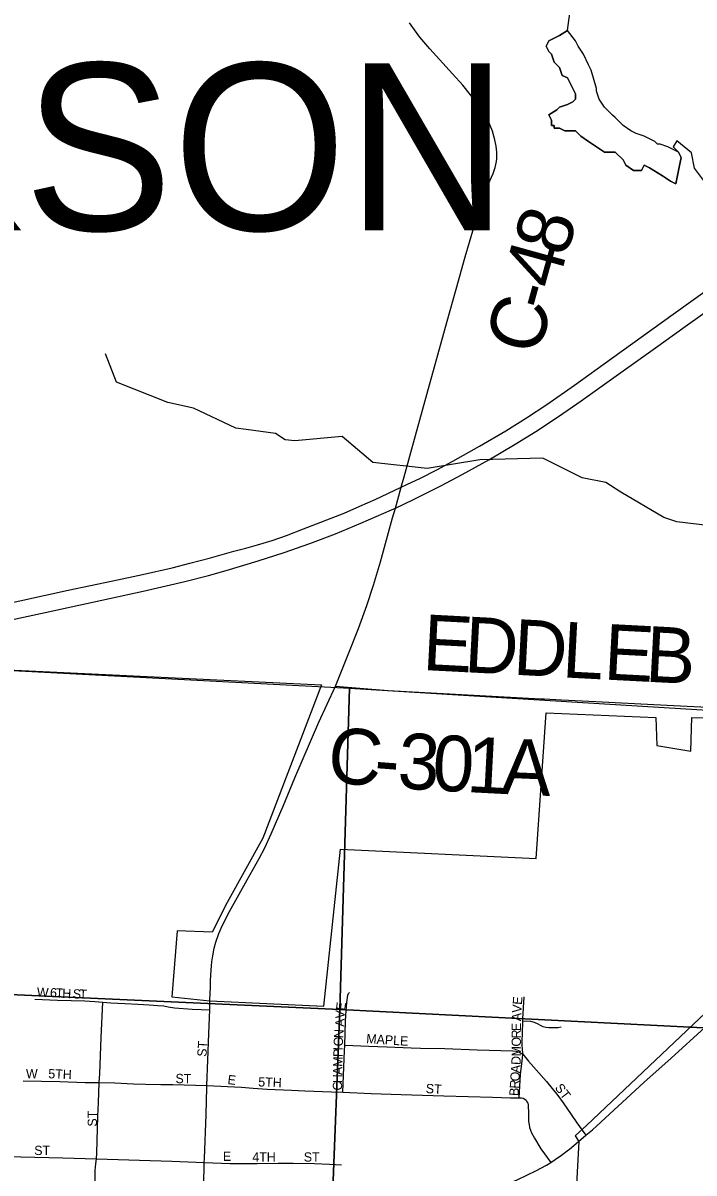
# Model space of a CAD drawing. Extents: x 0 to 34, y 0 to 22.
# Drawn here: x 4.796 to 5.481, y 18.295 to 19.468 of the extents above; entities that cross this region are included whole.
import ezdxf

# ---------------------------------------------------------------- set-up
doc = ezdxf.new("R2010")
doc.units = 0
for name, color, linetype in [('GM_X_City_Street', 7, 'Continuous'), ('GM_X_City_Street_Text', 7, 'Continuous'), ('GM_X_Corporation', 7, 'Continuous'), ('GM_X_County_Road', 7, 'Continuous'), ('GM_X_County_Road_Text', 7, 'Continuous'), ('GM_X_Minor_Lake', 7, 'Continuous'), ('GM_X_Minor_River', 7, 'Continuous'), ('GM_X_Section', 7, 'Continuous'), ('GM_X_State_Route', 7, 'Continuous'), ('GM_X_Township_Text', 7, 'Continuous')]:
    doc.layers.add(name, color=color, linetype=linetype)

msp = doc.modelspace()

# ---------------------------------------------------------------- linework, layer by layer
at = {"layer": 'GM_X_City_Street'}
for points in [[(4.8082, 18.4724), (4.8315, 18.4715), (4.8592, 18.4706), (4.8694, 18.4701), (4.8776, 18.4693)], [(4.9867, 18.4617), (4.987, 18.4717)], [(5.1257, 18.4562), (5.1265, 18.469), (5.1276, 18.4767), (5.1283, 18.4783), (5.1292, 18.4794)], [(5.306, 18.4503), (5.3061, 18.4523), (5.3074, 18.4749)], [(4.8741, 18.3874), (4.8746, 18.3964), (4.8761, 18.4333), (4.8776, 18.4693)], [(4.8776, 18.4693), (4.8859, 18.4688), (4.9001, 18.4681), (4.9135, 18.4673), (4.925, 18.4668), (4.9339, 18.4661), (4.9398, 18.4655), (4.9445, 18.4646), (4.9508, 18.4636), (4.9688, 18.4624), (4.9781, 18.4619), (4.9867, 18.4617)], [(4.9839, 18.3844), (4.9847, 18.4104), (4.9857, 18.4376), (4.9867, 18.4617)], [(5.1245, 18.4256), (5.1252, 18.4498), (5.1257, 18.4562)], [(5.3061, 18.4164), (5.3057, 18.4224), (5.3055, 18.4245), (5.3054, 18.4306), (5.3057, 18.4368), (5.306, 18.4503)], [(5.306, 18.4503), (5.3139, 18.4501), (5.3177, 18.4491), (5.3213, 18.4474), (5.3239, 18.4458), (5.3267, 18.4446), (5.3297, 18.4439), (5.3328, 18.4436), (5.339, 18.4435), (5.3421, 18.4437), (5.3451, 18.4442)], [(5.1225, 18.3775), (5.1243, 18.4201), (5.1245, 18.4256)], [(5.1245, 18.4256), (5.149, 18.4246), (5.1675, 18.4239), (5.1922, 18.4229), (5.2016, 18.4226), (5.2265, 18.4221), (5.2596, 18.4208), (5.2961, 18.4197), (5.2992, 18.4193), (5.302, 18.4186), (5.3061, 18.4164)], [(5.3023, 18.372), (5.3039, 18.3958), (5.3057, 18.4122), (5.3061, 18.4164)], [(5.3061, 18.4164), (5.312, 18.4093), (5.3302, 18.3884), (5.3419, 18.3741), (5.3474, 18.3668), (5.3554, 18.3549)], [(4.7965, 18.3893), (4.8337, 18.3884), (4.8595, 18.3876), (4.8717, 18.3874), (4.8741, 18.3874)], [(4.8711, 18.3097), (4.8717, 18.3153), (4.8727, 18.3532), (4.8732, 18.3666), (4.8741, 18.3874)], [(4.8741, 18.3874), (4.89, 18.387), (4.9089, 18.3863), (4.9212, 18.3859), (4.9367, 18.3855), (4.9491, 18.3854), (4.9839, 18.3844)], [(4.9811, 18.3058), (4.9813, 18.3101), (4.983, 18.3548), (4.9838, 18.3825), (4.9839, 18.3844)], [(4.9839, 18.3844), (5.019, 18.3827), (5.0311, 18.3817), (5.0452, 18.3808), (5.07, 18.3796), (5.0836, 18.3789), (5.111, 18.3779), (5.1225, 18.3775)], [(5.1225, 18.3775), (5.1513, 18.3763), (5.1822, 18.3753), (5.2256, 18.3738), (5.2752, 18.3725), (5.2845, 18.3723), (5.2937, 18.372), (5.3023, 18.372)], [(5.3023, 18.372), (5.3031, 18.3719), (5.3049, 18.3717), (5.3064, 18.3714), (5.3082, 18.3705), (5.3094, 18.3694), (5.3104, 18.3679), (5.3111, 18.3664), (5.3115, 18.365), (5.3117, 18.3632), (5.3119, 18.3568), (5.3119, 18.3507), (5.3121, 18.3476), (5.3125, 18.3446), (5.3131, 18.3417), (5.314, 18.3388), (5.3151, 18.336), (5.3179, 18.3306), (5.3245, 18.32), (5.3347, 18.3059)], [(5.3554, 18.3549), (5.3612, 18.3464), (5.3667, 18.3389), (5.3706, 18.3337)], [(5.3347, 18.3059), (5.3392, 18.3089), (5.3455, 18.3134), (5.3528, 18.3188)], [(4.7094, 18.3139), (4.7939, 18.3118), (4.8368, 18.3107), (4.8711, 18.3097)], [(4.8682, 18.2305), (4.8687, 18.2363), (4.8694, 18.2629), (4.8698, 18.2978), (4.8705, 18.3045), (4.8711, 18.3097)], [(4.8711, 18.3097), (4.9481, 18.3074), (4.9728, 18.3064), (4.9811, 18.3058)], [(4.98, 18.2664), (4.981, 18.2999), (4.9811, 18.3058)], [(4.9811, 18.3058), (5.0075, 18.305), (5.0352, 18.305), (5.0567, 18.3052), (5.072, 18.3051), (5.0935, 18.3048), (5.1088, 18.3042), (5.1211, 18.3034)], [(5.1151, 18.2271), (5.1191, 18.2276), (5.1284, 18.2294), (5.1375, 18.2316), (5.1525, 18.2361), (5.2263, 18.2613), (5.2647, 18.2746), (5.2852, 18.2822), (5.2997, 18.288), (5.311, 18.2933), (5.3194, 18.2975), (5.3303, 18.3032), (5.3347, 18.3059)]]:
    msp.add_lwpolyline(points, dxfattribs=at)
at = {"layer": 'GM_X_Corporation'}
for points in [[(4.7237, 18.8109), (5.1009, 18.7931), (5.0408, 18.6366), (5.0045, 18.5712), (4.9891, 18.5408), (4.9534, 18.542), (4.948, 18.4748), (4.987, 18.4706), (5.1033, 18.4653), (5.12, 18.6253), (5.3198, 18.6158), (5.33, 18.7645), (5.4418, 18.7598), (5.443, 18.7312), (5.4775, 18.7253), (5.4787, 18.7598), (5.7821, 18.7586)], [(5.6005, 18.5608), (5.3716, 18.3439), (5.3597, 18.3332), (5.3632, 18.3273), (5.329, 17.6967)]]:
    msp.add_lwpolyline(points, dxfattribs=at)
at = {"layer": 'GM_X_County_Road'}
for points in [[(5.1151, 18.7918), (5.1294, 18.8274), (5.1385, 18.8505), (5.1469, 18.8739), (5.1537, 18.8946), (5.1608, 18.9184), (5.1733, 18.9633), (5.1761, 18.9733), (5.182, 18.9945), (5.1824, 18.996), (5.185, 19.0052), (5.1967, 19.0471), (5.2081, 19.089), (5.2291, 19.1637), (5.2382, 19.1966), (5.2474, 19.2295), (5.2561, 19.2593), (5.2612, 19.2772), (5.2649, 19.2889), (5.2672, 19.2946), (5.2708, 19.3031), (5.2758, 19.3145), (5.2778, 19.3205), (5.2786, 19.3236), (5.2792, 19.3267), (5.2795, 19.3298), (5.2796, 19.333), (5.2795, 19.3361), (5.2789, 19.3424), (5.2777, 19.3486), (5.2751, 19.3576), (5.273, 19.3635), (5.2704, 19.3692), (5.2673, 19.3746), (5.2639, 19.3798), (5.2585, 19.3874), (5.2529, 19.3948), (5.245, 19.4045), (5.2345, 19.4159), (5.2114, 19.4417), (5.2011, 19.4536), (5.1956, 19.4608), (5.1907, 19.4682)], [(4.987, 18.4717), (4.9875, 18.4846), (4.9875, 18.4908), (4.9879, 18.4974), (4.9884, 18.5065), (4.9889, 18.5106), (4.9898, 18.5167), (4.9913, 18.5244), (4.9929, 18.5305), (4.996, 18.5394), (4.9997, 18.548), (5.0069, 18.5618), (5.0251, 18.5943), (5.0373, 18.6158), (5.043, 18.6268), (5.0494, 18.6409), (5.0615, 18.6694), (5.0735, 18.698), (5.0982, 18.7549), (5.1151, 18.7918)], [(5.1151, 18.7918), (5.1689, 18.7871), (5.2188, 18.7844), (5.3246, 18.7788)], [(5.3246, 18.7788), (5.328, 18.7787), (5.3455, 18.7777), (5.3805, 18.776), (5.4397, 18.773), (5.4805, 18.771), (5.5819, 18.766), (5.5842, 18.7659), (5.6253, 18.7634), (5.637, 18.7629), (5.6439, 18.7625), (5.6526, 18.7624), (5.6595, 18.7622), (5.6719, 18.7626), (5.6733, 18.7627), (5.6792, 18.7633), (5.6872, 18.7642), (5.6892, 18.7644), (5.6965, 18.765), (5.7135, 18.766), (5.7139, 18.766)], [(5.3706, 18.3337), (5.3771, 18.3393), (5.4295, 18.3876), (5.4574, 18.4124), (5.4918, 18.4437), (5.5399, 18.4876), (5.6294, 18.5692), (5.6663, 18.6024), (5.7055, 18.6377), (5.7331, 18.6628)], [(5.3528, 18.3188), (5.3539, 18.3196), (5.3581, 18.3232), (5.3631, 18.3273), (5.3706, 18.3337)]]:
    msp.add_lwpolyline(points, dxfattribs=at)
at = {"layer": 'GM_X_Minor_Lake'}
for points in [[(5.3517, 19.4604), (5.3436, 19.455), (5.3382, 19.4523), (5.3328, 19.4496), (5.3301, 19.4442), (5.3328, 19.4388), (5.3355, 19.4361), (5.3382, 19.428), (5.3436, 19.4226), (5.3463, 19.4145), (5.3517, 19.4118), (5.3598, 19.3956), (5.3598, 19.3902), (5.3571, 19.3875), (5.3517, 19.3848), (5.3436, 19.3821), (5.3409, 19.3794), (5.3328, 19.3741), (5.3355, 19.3687), (5.3355, 19.3633), (5.3382, 19.3633), (5.3382, 19.3606), (5.3409, 19.3606), (5.3436, 19.3606), (5.349, 19.3579), (5.3571, 19.3579), (5.3598, 19.3579), (5.3652, 19.3525), (5.3733, 19.3471), (5.3814, 19.3417), (5.3895, 19.3363), (5.4003, 19.3363), (5.4084, 19.3282), (5.4111, 19.3228), (5.4192, 19.3174), (5.4273, 19.3174), (5.43, 19.3228), (5.4354, 19.3201), (5.4488, 19.312), (5.4569, 19.3066), (5.4623, 19.3039), (5.465, 19.3174), (5.4677, 19.3309), (5.465, 19.3363)], [(5.4596, 19.3417), (5.465, 19.3363), (5.4677, 19.3309), (5.465, 19.3174), (5.4623, 19.3039), (5.4569, 19.3066), (5.4488, 19.312), (5.4354, 19.3201), (5.43, 19.3228), (5.4273, 19.3174), (5.4192, 19.3174), (5.4111, 19.3228), (5.4084, 19.3282), (5.4003, 19.3363), (5.3895, 19.3363), (5.3814, 19.3417), (5.3733, 19.3471), (5.3652, 19.3525), (5.3598, 19.3579), (5.3571, 19.3579), (5.349, 19.3579), (5.3436, 19.3606), (5.3409, 19.3606), (5.3382, 19.3606), (5.3382, 19.3633), (5.3355, 19.3633), (5.3355, 19.3687), (5.3328, 19.3741), (5.3409, 19.3794), (5.3436, 19.3821), (5.3517, 19.3848), (5.3571, 19.3875), (5.3598, 19.3902), (5.3598, 19.3956), (5.3517, 19.4118), (5.3463, 19.4145), (5.3436, 19.4226), (5.3382, 19.428), (5.3355, 19.4361), (5.3328, 19.4388), (5.3301, 19.4442), (5.3328, 19.4496), (5.3382, 19.4523), (5.3436, 19.455), (5.3517, 19.4604)], [(5.465, 19.3363), (5.4542, 19.3417), (5.4462, 19.3444), (5.4434, 19.3444), (5.4408, 19.3471), (5.43, 19.3525), (5.4219, 19.3552), (5.4165, 19.3579), (5.4084, 19.3633), (5.4003, 19.3714), (5.3976, 19.374), (5.3895, 19.3821), (5.3841, 19.3902), (5.3814, 19.3983), (5.3814, 19.401), (5.376, 19.4199), (5.3733, 19.4253), (5.3679, 19.4361), (5.3625, 19.4442), (5.3598, 19.4496), (5.3517, 19.4604)]]:
    msp.add_lwpolyline(points, dxfattribs=at)
at = {"layer": 'GM_X_Minor_River'}
for points in [[(5.3517, 19.4604), (5.3585, 19.5113)], [(5.547, 18.9106), (5.556, 18.9383), (5.5661, 18.9558), (5.5754, 18.9862), (5.5712, 19.0108), (5.5662, 19.0214), (5.5654, 19.0347), (5.5672, 19.0442), (5.5777, 19.0643), (5.5879, 19.0701), (5.5932, 19.0807), (5.5719, 19.1148), (5.5769, 19.1649), (5.5731, 19.1755), (5.5587, 19.1895), (5.5461, 19.1966), (5.5244, 19.2292), (5.5194, 19.2459), (5.5197, 19.261), (5.517, 19.2724), (5.4813, 19.3197), (5.4782, 19.3356), (5.4633, 19.3477), (5.4596, 19.3417)], [(5.5487, 18.9092), (5.5371, 18.9341), (5.5275, 18.9462), (5.5173, 18.9526), (5.4631, 18.9592), (5.4499, 18.9637), (5.4062, 18.9894), (5.391, 18.9992), (5.3668, 19.004), (5.3266, 19.024), (5.2622, 19.0223), (5.2085, 19.0137), (5.1532, 19.0196), (5.122, 19.0461), (5.0736, 19.0417), (5.0638, 19.0429), (5.0539, 19.0493), (5.024, 19.0533), (5.0134, 19.0548), (4.9701, 19.0752), (4.944, 19.0808), (4.8916, 19.1015), (4.8805, 19.1306)]]:
    msp.add_lwpolyline(points, dxfattribs=at)
at = {"layer": 'GM_X_Section'}
for points in [[(4.1194, 18.8444), (4.1236, 18.8442), (4.6166, 18.8164), (5.1167, 18.7903), (5.1294, 18.7895), (5.1195, 18.4619), (4.1166, 18.5074)], [(5.6053, 18.7602), (6.1384, 18.7353), (6.1311, 18.4108), (5.1195, 18.4619), (5.1294, 18.7895)], [(4.1166, 18.5074), (5.1195, 18.4619), (5.0805, 17.4591), (4.0746, 17.5111)], [(5.1195, 18.4619), (6.1311, 18.4108), (6.125, 18.2446), (6.1067, 17.7389), (6.0962, 17.4141), (5.0805, 17.4591)]]:
    msp.add_lwpolyline(points, close=True, dxfattribs=at)
at = {"layer": 'GM_X_State_Route'}
for points in [[(4.7694, 18.8735), (4.8423, 18.8894), (4.8879, 18.899), (4.9182, 18.9055), (4.9485, 18.9124), (4.9666, 18.9169), (4.9876, 18.9225), (5.0115, 18.9293), (5.0236, 18.9323), (5.0355, 18.9357), (5.0504, 18.9403), (5.0651, 18.9454), (5.0825, 18.9521), (5.1239, 18.9681), (5.1398, 18.9752), (5.1554, 18.9819), (5.182, 18.9945), (5.1878, 18.9972), (5.2018, 19.0038), (5.2184, 19.0123), (5.2349, 19.0212), (5.262, 19.0363), (5.2888, 19.0521), (5.3099, 19.0653), (5.3306, 19.079), (5.3587, 19.0985), (5.3965, 19.1258), (5.4596, 19.1711), (5.5278, 19.2199)], [(4.749, 18.8519), (4.8188, 18.8669), (4.919, 18.8886), (4.9613, 18.8984), (4.9854, 18.9045), (5.0034, 18.9095), (5.036, 18.9193), (5.0626, 18.9279), (5.089, 18.9372), (5.1151, 18.9471), (5.1409, 18.9578), (5.1722, 18.9715), (5.1761, 18.9733), (5.1947, 18.982), (5.2225, 18.9958), (5.2444, 19.0074), (5.2715, 19.0226), (5.2983, 19.0383), (5.3194, 19.0514), (5.3427, 19.0667), (5.3657, 19.0827), (5.4062, 19.1115), (5.4415, 19.1367), (5.4718, 19.1584), (5.5199, 19.1928)]]:
    msp.add_lwpolyline(points, dxfattribs=at)

# ---------------------------------------------------------------- texts
at = {"layer": 'GM_X_City_Street_Text'}
for s, rotation, p in [('W', 357.1242, (4.8102, 18.4751)), ('6', 357.1064, (4.8236, 18.4745)), ('T', 357.1021, (4.8294, 18.4742)), ('H', 357.1106, (4.8361, 18.4738)), ('S', 357.1021, (4.8469, 18.4733)), ('T', 357.6042, (4.8536, 18.473)), ('E', 85.7606, (5.3052, 18.4665)), ('V', 85.7555, (5.1242, 18.4523)), ('E', 82.6039, (5.1248, 18.4605)), ('A', 87.0263, (5.3042, 18.4499)), ('V', 85.8443, (5.3046, 18.4582)), ('A', 89.7814, (5.1242, 18.4442)), ('E', 89.9956, (5.3042, 18.4399)), ('N', 86.8068, (5.1229, 18.4325)), ('MAPLE', 356.3473, (5.1462, 18.4276)), ('R', 89.994, (5.3042, 18.4324)), ('ST', 86.4118, (4.9834, 18.4135)), ('O', 87.4639, (5.1225, 18.4242)), ('O', 89.9928, (5.3042, 18.4241)), ('M', 89.6531, (5.3042, 18.414)), ('M', 88.9617, (5.1221, 18.4034)), ('P', 88.9893, (5.1223, 18.4134)), ('I', 88.6444, (5.1224, 18.42)), ('D', 87.1667, (5.3037, 18.4052)), ('W', 0, (4.7993, 18.3918)), ('5TH', 357.7021, (4.8219, 18.3918)), ('A', 88.9727, (5.122, 18.3951)), ('A', 86.3691, (5.3032, 18.3968)), ('ST', 0, (4.9518, 18.3868)), ('E', 352.8514, (5.0045, 18.386)), ('5TH', 357.7108, (5.0361, 18.3835)), ('C', 88.9557, (5.1217, 18.3792)), ('H', 88.9794, (5.1218, 18.3867)), ('R', 86.3667, (5.3022, 18.381)), ('O', 86.3673, (5.3027, 18.3884)), ('ST', 356.4254, (5.2069, 18.3768)), ('B', 86.3555, (5.3017, 18.3735)), ('ST', 307.5776, (5.3383, 18.3819)), ('ST', 90, (4.8717, 18.3425)), ('ST', 0, (4.8077, 18.3135)), ('E', 0, (5.0002, 18.3076)), ('4TH', 0, (5.0302, 18.3068)), ('ST', 0, (5.0827, 18.3068))]:
    msp.add_text(s, height=0.00947, rotation=rotation, dxfattribs=at).set_placement(p)
at = {"layer": 'GM_X_County_Road_Text'}
for s, rotation, p in [('8', 72.6084, (5.3498, 19.2279)), ('4', 74.5335, (5.3406, 19.1947)), ('-', 74.5929, (5.3344, 19.1722)), ('C', 74.6138, (5.322, 19.1272)), ('E', 357.0073, (5.2031, 18.8082)), ('D', 357.0043, (5.2456, 18.806)), ('D', 357.0079, (5.2955, 18.8034)), ('L', 357.003, (5.3454, 18.8007)), ('E', 357.0078, (5.3879, 18.7985)), ('B', 357.0068, (5.4303, 18.7963)), ('C', 354.1158, (5.1052, 18.6944)), ('3', 356.5623, (5.1775, 18.6876)), ('0', 356.9932, (5.2129, 18.6855)), ('1', 357.0225, (5.2479, 18.6837)), ('A', 357.5211, (5.2834, 18.6818)), ('-', 355.6814, (5.1533, 18.6895))]:
    msp.add_text(s, height=0.0568, rotation=rotation, dxfattribs=at).set_placement(p)
at = {"layer": 'GM_X_Township_Text'}
msp.add_text('JACKSON', height=0.17045, rotation=0, dxfattribs=at).set_placement((4.2144, 19.2564))

doc.saveas('drawing.dxf')
